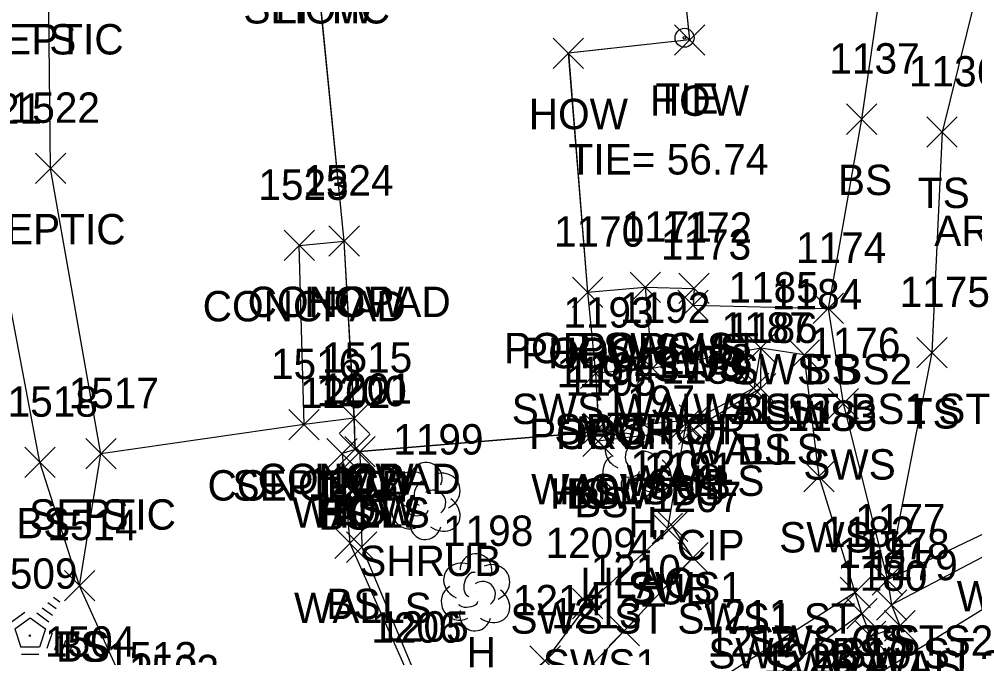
# Model space of a CAD drawing. Extents: x 1512665 to 1513714, y 110636 to 112816.
# Drawn here: x 1513101.2 to 1513164.2, y 110977 to 111019.1 of the extents above; entities that cross this region are included whole.
import ezdxf

# ---------------------------------------------------------------- set-up
doc = ezdxf.new("R2010")
doc.units = 0
for name, color, linetype in [('C_A', 7, 'Continuous'), ('C_C', 7, 'Continuous'), ('CBP', 7, 'Continuous'), ('L_A', 7, 'Continuous'), ('L_C', 7, 'Continuous'), ('L_I', 7, 'Continuous'), ('L_TIC', 7, 'Continuous'), ('LBC', 7, 'Continuous'), ('LBF', 7, 'Continuous'), ('LELB', 7, 'Continuous'), ('Level 13', 7, 'Continuous'), ('LS', 7, 'Continuous'), ('LSH', 7, 'Continuous'), ('LTC', 7, 'Continuous'), ('LTD', 7, 'Continuous'), ('LWS', 7, 'Continuous'), ('P_I', 7, 'Continuous'), ('PEU', 7, 'Continuous'), ('R_A', 7, 'Continuous'), ('R_I', 7, 'Continuous'), ('R_TIC', 7, 'Continuous'), ('RSW', 7, 'Continuous'), ('U_A', 7, 'Continuous'), ('U_C', 7, 'Continuous'), ('U_I', 7, 'Continuous'), ('U_TIC', 7, 'Continuous'), ('USA', 7, 'Continuous'), ('UUU', 7, 'Continuous')]:
    doc.layers.add(name, color=color, linetype=linetype)

msp = doc.modelspace()

# ---------------------------------------------------------------- linework, layer by layer
at = {"layer": 'CBP'}
for radius in [0.625, 0.0833]:
    msp.add_circle((1513145.031, 111017.845), radius, dxfattribs=at)
at = {"layer": 'L_TIC'}
for points in [[(1513144.361, 111016.708), (1513146.361, 111018.708)], [(1513146.361, 111016.708), (1513144.361, 111018.708)], [(1513136.385, 111015.829), (1513138.385, 111017.829)], [(1513138.385, 111015.829), (1513136.385, 111017.829)], [(1513155.691, 111011.489), (1513157.691, 111013.489)], [(1513157.691, 111011.489), (1513155.691, 111013.489)], [(1513160.988, 111010.639), (1513162.988, 111012.639)], [(1513162.988, 111010.639), (1513160.988, 111012.639)], [(1513118.654, 111003.177), (1513120.654, 111005.177)], [(1513120.654, 111003.177), (1513118.654, 111005.177)], [(1513121.614, 111003.463), (1513123.614, 111005.463)], [(1513123.614, 111003.463), (1513121.614, 111005.463)], [(1513121.614, 111003.463), (1513123.614, 111005.463)], [(1513123.614, 111003.463), (1513121.614, 111005.463)], [(1513137.645, 111000.096), (1513139.645, 111002.096)], [(1513139.645, 111000.096), (1513137.645, 111002.096)], [(1513137.645, 111000.096), (1513139.645, 111002.096)], [(1513139.645, 111000.096), (1513137.645, 111002.096)], [(1513141.447, 111000.421), (1513143.447, 111002.421)], [(1513143.447, 111000.421), (1513141.447, 111002.421)], [(1513153.494, 110999.03), (1513155.494, 111001.03)], [(1513155.494, 110999.03), (1513153.494, 111001.03)], [(1513149.05, 110996.419), (1513151.05, 110998.419)], [(1513151.05, 110996.419), (1513149.05, 110998.419)], [(1513149.05, 110996.419), (1513151.05, 110998.419)], [(1513151.05, 110996.419), (1513149.05, 110998.419)], [(1513160.319, 110996.122), (1513162.319, 110998.122)], [(1513162.319, 110996.122), (1513160.319, 110998.122)], [(1513141.906, 110995.079), (1513143.906, 110997.079)], [(1513143.906, 110995.079), (1513141.906, 110997.079)], [(1513138.172, 110994.766), (1513140.172, 110996.766)], [(1513140.172, 110994.766), (1513138.172, 110996.766)], [(1513138.172, 110994.766), (1513140.172, 110996.766)], [(1513140.172, 110994.766), (1513138.172, 110996.766)], [(1513148.586, 110993.774), (1513150.586, 110995.774)], [(1513150.586, 110993.774), (1513148.586, 110995.774)], [(1513149.035, 110993.75), (1513151.035, 110995.75)], [(1513151.035, 110993.75), (1513149.035, 110995.75)], [(1513122.275, 110991.806), (1513124.275, 110993.806)], [(1513124.275, 110991.806), (1513122.275, 110993.806)], [(1513122.275, 110991.806), (1513124.275, 110993.806)], [(1513124.275, 110991.806), (1513122.275, 110993.806)], [(1513118.973, 110991.381), (1513120.973, 110993.381)], [(1513120.973, 110991.381), (1513118.973, 110993.381)], [(1513138.383, 110991.132), (1513140.383, 110993.132)], [(1513140.383, 110991.132), (1513138.383, 110993.132)], [(1513138.383, 110991.132), (1513140.383, 110993.132)], [(1513140.383, 110991.132), (1513138.383, 110993.132)], [(1513144.678, 110991.69), (1513146.678, 110993.69)], [(1513146.678, 110991.69), (1513144.678, 110993.69)], [(1513137.775, 110990.845), (1513139.775, 110992.845)], [(1513139.775, 110990.845), (1513137.775, 110992.845)], [(1513137.775, 110990.845), (1513139.775, 110992.845)], [(1513139.775, 110990.845), (1513137.775, 110992.845)], [(1513144.641, 110991.07), (1513146.641, 110993.07)], [(1513146.641, 110991.07), (1513144.641, 110993.07)], [(1513138.327, 110990.282), (1513140.327, 110992.282)], [(1513140.327, 110990.282), (1513138.327, 110992.282)], [(1513105.594, 110989.463), (1513107.594, 110991.463)], [(1513107.594, 110989.463), (1513105.594, 110991.463)], [(1513121.48, 110989.47), (1513123.48, 110991.47)], [(1513123.48, 110989.47), (1513121.48, 110991.47)], [(1513122.337, 110989.753), (1513124.337, 110991.753)], [(1513124.337, 110989.753), (1513122.337, 110991.753)], [(1513122.337, 110989.753), (1513124.337, 110991.753)], [(1513124.337, 110989.753), (1513122.337, 110991.753)], [(1513122.648, 110989.593), (1513124.648, 110991.593)], [(1513124.648, 110989.593), (1513122.648, 110991.593)], [(1513122.648, 110989.593), (1513124.648, 110991.593)], [(1513124.648, 110989.593), (1513122.648, 110991.593)], [(1513101.575, 110988.899), (1513103.575, 110990.899)], [(1513103.575, 110988.899), (1513101.575, 110990.899)], [(1513121.993, 110983.577), (1513123.993, 110985.577)], [(1513123.993, 110983.577), (1513121.993, 110985.577)], [(1513122.771, 110983.314), (1513124.771, 110985.314)], [(1513124.771, 110983.314), (1513122.771, 110985.314)], [(1513157.395, 110981.164), (1513159.395, 110983.164)], [(1513159.395, 110981.164), (1513157.395, 110983.164)], [(1513157.395, 110981.164), (1513159.395, 110983.164)], [(1513159.395, 110981.164), (1513157.395, 110983.164)], [(1513104.188, 110980.774), (1513106.188, 110982.774)], [(1513106.188, 110980.774), (1513104.188, 110982.774)], [(1513104.188, 110980.774), (1513106.188, 110982.774)], [(1513106.188, 110980.774), (1513104.188, 110982.774)], [(1513155.276, 110980.329), (1513157.276, 110982.329)], [(1513157.276, 110980.329), (1513155.276, 110982.329)], [(1513157.665, 110979.511), (1513159.665, 110981.511)], [(1513159.665, 110979.511), (1513157.665, 110981.511)], [(1513155.717, 110978.943), (1513157.717, 110980.943)], [(1513157.717, 110978.943), (1513155.717, 110980.943)]]:
    msp.add_lwpolyline(points, dxfattribs=at)
at = {"layer": 'LBC'}
msp.add_lwpolyline([(1513118.388, 111046.131), (1513128.974, 111047.21), (1513141.844, 111048.525), (1513143.285, 111036.994), (1513150.612, 111037.656), (1513151.294, 111036.531), (1513151.864, 111031.982), (1513152.237, 111029.894), (1513144.204, 111028.943), (1513145.361, 111017.708), (1513137.385, 111016.829), (1513138.645, 111001.096), (1513139.172, 110995.766), (1513139.383, 110992.132), (1513138.775, 110991.845), (1513123.648, 110990.593), (1513123.337, 110990.753), (1513123.275, 110992.806), (1513122.614, 111004.463), (1513120.694, 111023.787), (1513118.555, 111043.769)], dxfattribs=at)
at = {"layer": 'LBF'}
msp.add_lwpolyline([(1513138.645, 111001.096), (1513142.447, 111001.421), (1513142.906, 110996.079), (1513139.172, 110995.766)], dxfattribs=at)
at = {"layer": 'LELB'}
for points in [[(1513170.214, 111130.816), (1513170.8, 111112.207), (1513173.531, 111089.539), (1513174.355, 111074.616), (1513179.798, 111058.724), (1513184.877, 111038.844), (1513186.524, 111012.71), (1513182.7, 110990.922), (1513167.492, 110986.513), (1513158.395, 110982.164)], [(1513152.471, 111070.911), (1513151.073, 111055.043), (1513161.472, 111056.619), (1513164.142, 111042.453), (1513166.779, 111030.992), (1513161.988, 111011.639), (1513161.319, 110997.122), (1513158.395, 110982.164)], [(1513105.188, 110981.774), (1513102.575, 110989.899), (1513098.9, 111009.187), (1513096.17, 111015.48), (1513093.494, 111029.55), (1513095.063, 111040.188), (1513092.913, 111045.41), (1513085.194, 111066.711)], [(1513153.398, 111047.966), (1513157.531, 111038.71), (1513159.125, 111029.326), (1513156.691, 111012.489), (1513154.494, 111000.03)], [(1513150.05, 110997.419), (1513150.035, 110994.75), (1513145.641, 110992.07), (1513139.327, 110991.282), (1513138.775, 110991.845)], [(1513123.337, 110990.753), (1513122.48, 110990.47), (1513122.993, 110984.577), (1513127.225, 110975.026), (1513127.998, 110970.168), (1513130.147, 110967.663)], [(1513116.012, 110958.893), (1513109.111, 110973.071), (1513105.188, 110981.774), (1513106.594, 110990.463)], [(1513156.276, 110981.329), (1513147.675, 110975.841), (1513130.86, 110966.117), (1513127.367, 110963.559), (1513113.24, 110946.252), (1513110.297, 110944.595), (1513100.487, 110942.417), (1513099.399, 110932.182), (1513097.199, 110922.304)]]:
    msp.add_lwpolyline(points, dxfattribs=at)
at = {"layer": 'Level 13'}
msp.add_lwpolyline([(1513123.644, 110990.606), (1513123.347, 110990.764), (1513123.285, 110992.81), (1513122.624, 111004.459), (1513120.705, 111023.788), (1513118.567, 111043.766), (1513118.402, 111046.123), (1513128.978, 111047.2), (1513141.835, 111048.514), (1513143.273, 111036.981), (1513150.611, 111037.648), (1513151.284, 111036.528), (1513151.853, 111031.979), (1513152.224, 111029.902), (1513144.191, 111028.956), (1513145.349, 111017.72), (1513137.373, 111016.842), (1513138.634, 111001.097), (1513139.163, 110995.765), (1513139.374, 110992.138), (1513138.775, 110991.854)], close=True, dxfattribs=at)
at = {"layer": 'LS'}
msp.add_lwpolyline([(1513123.275, 110992.806), (1513119.973, 110992.381), (1513119.654, 111004.177), (1513122.614, 111004.463)], dxfattribs=at)
at = {"layer": 'LSH'}
msp.add_line((1513127.977, 110987.411), (1513127.977, 110987.411), dxfattribs=at)
msp.add_line((1513127.977, 110987.411), (1513127.977, 110987.411), dxfattribs=at)
msp.add_arc((1513128.023, 110988.845), 1.047, 335.52715, 180.95627, dxfattribs=at)
for centre, major_axis, ratio, start_param, end_param in [((1513127.185, 110988.078), (1.21, -0.512), 0.895232, 1.570796, 4.712389), ((1513129.018, 110987.995), (-1.141, -0.483), 0.949671, 1.570796, 4.712389), ((1513127.768, 110987.87), (-0.208, -0.792), 0.645439, 3.141593, 6.283185), ((1513128.477, 110987.245), (-0.5, 0.667), 0.989748, 3.141593, 6.283185), ((1513126.893, 110986.703), (0.584, -1.042), 0.959034, 3.141593, 6.283185), ((1513128.977, 110986.578), (-1.09, 0.792), 0.841452, 1.570796, 4.712389), ((1513127.518, 110986.661), (-0.625, -0.083), 0.423636, 0, 3.141593), ((1513127.977, 110985.911), (0.265, 1.061), 0.942809, 1.570796, 4.712389)]:
    msp.add_ellipse(centre, major_axis=major_axis, ratio=ratio, start_param=start_param, end_param=end_param, dxfattribs=at)
at = {"layer": 'LTC'}
for p, q in [((1513103.107, 110980.678), (1513103.657, 110980.279)), ((1513103.479, 110981.027), (1513103.898, 110980.722)), ((1513100.709, 110979.389), (1513101.587, 110980.027)), ((1513102.365, 110979.982), (1513103.175, 110979.393)), ((1513102.737, 110980.33), (1513103.416, 110979.836)), ((1513100.934, 110978.934), (1513101.945, 110979.669)), ((1513101.945, 110979.669), (1513102.942, 110978.944)), ((1513100.934, 110978.934), (1513101.321, 110977.741)), ((1513102.942, 110978.944), (1513102.551, 110977.741)), ((1513103.38, 110978.673), (1513103.042, 110977.633)), ((1513103.824, 110978.422), (1513103.537, 110977.538)), ((1513104.269, 110978.172), (1513104.032, 110977.443)), ((1513102.551, 110977.741), (1513101.321, 110977.741)), ((1513104.713, 110977.922), (1513104.527, 110977.348)), ((1513102.513, 110977.241), (1513101.368, 110977.241))]:
    msp.add_line(p, q, dxfattribs=at)
at = {"layer": 'LTD'}
for p, q in [((1513141.89, 110989.956), (1513141.89, 110989.956)), ((1513141.89, 110989.956), (1513141.89, 110989.956)), ((1513131.249, 110981.395), (1513131.249, 110981.395)), ((1513131.249, 110981.395), (1513131.249, 110981.395))]:
    msp.add_line(p, q, dxfattribs=at)
for centre in [(1513141.937, 110991.39), (1513131.295, 110982.829)]:
    msp.add_arc(centre, 1.047, 335.52715, 180.95627, dxfattribs=at)
for centre, major_axis, ratio, start_param, end_param in [((1513141.098, 110990.622), (1.21, -0.512), 0.895232, 1.570796, 4.712389), ((1513142.932, 110990.539), (-1.141, -0.483), 0.949671, 1.570796, 4.712389), ((1513141.682, 110990.414), (-0.208, -0.792), 0.645439, 3.141593, 6.283185), ((1513142.39, 110989.789), (-0.5, 0.667), 0.989748, 3.141593, 6.283185), ((1513140.807, 110989.247), (0.584, -1.042), 0.959034, 3.141593, 6.283185), ((1513142.89, 110989.123), (-1.09, 0.792), 0.841452, 1.570796, 4.712389), ((1513141.89, 110988.456), (0.265, 1.061), 0.942809, 1.570796, 4.712389), ((1513141.432, 110989.206), (-0.625, -0.083), 0.423636, 0, 3.141593), ((1513130.457, 110982.062), (1.21, -0.512), 0.895232, 1.570796, 4.712389), ((1513132.29, 110981.979), (-1.141, -0.483), 0.949671, 1.570796, 4.712389), ((1513131.04, 110981.853), (-0.208, -0.792), 0.645439, 3.141593, 6.283185), ((1513131.749, 110981.229), (-0.5, 0.667), 0.989748, 3.141593, 6.283185), ((1513130.165, 110980.687), (0.584, -1.042), 0.959034, 3.141593, 6.283185), ((1513132.249, 110980.562), (-1.09, 0.792), 0.841452, 1.570796, 4.712389), ((1513130.79, 110980.645), (-0.625, -0.083), 0.423636, 0, 3.141593), ((1513131.249, 110979.895), (0.265, 1.061), 0.942809, 1.570796, 4.712389)]:
    msp.add_ellipse(centre, major_axis=major_axis, ratio=ratio, start_param=start_param, end_param=end_param, dxfattribs=at)
at = {"layer": 'LWS'}
for points in [[(1513150.05, 110997.419), (1513149.586, 110994.774), (1513145.678, 110992.69), (1513139.383, 110992.132)], [(1513190.646, 110994.729), (1513182.7, 110990.922), (1513167.412, 110985.094), (1513158.665, 110980.511)], [(1513123.648, 110990.593), (1513123.771, 110984.314), (1513127.636, 110975.095), (1513128.797, 110970.683)], [(1513156.717, 110979.943), (1513148.678, 110974.104), (1513134.451, 110961.665)]]:
    msp.add_lwpolyline(points, dxfattribs=at)
at = {"layer": 'PEU'}
msp.add_lwpolyline([(1513166.519, 110981.347), (1513152.909, 110972.975), (1513141.651, 110962.521), (1513132.856, 110956.743), (1513121.044, 110940.287), (1513117.581, 110922.155), (1513113.236, 110898.634), (1513114.597, 110873.193), (1513114.571, 110845.124), (1513110.002, 110827.884), (1513105.721, 110820.37), (1513100.887, 110809.465), (1513086.517, 110797.2)], dxfattribs=at)
at = {"layer": 'R_TIC'}
for points in [[(1513141.447, 111000.421), (1513143.447, 111002.421)], [(1513143.447, 111000.421), (1513141.447, 111002.421)], [(1513144.658, 111000.352), (1513146.658, 111002.352)], [(1513146.658, 111000.352), (1513144.658, 111002.352)], [(1513144.592, 110999.235), (1513146.592, 111001.235)], [(1513146.592, 110999.235), (1513144.592, 111001.235)], [(1513153.494, 110999.03), (1513155.494, 111001.03)], [(1513155.494, 110999.03), (1513153.494, 111001.03)], [(1513149.05, 110996.419), (1513151.05, 110998.419)], [(1513151.05, 110996.419), (1513149.05, 110998.419)], [(1513151.91, 110995.965), (1513153.91, 110997.965)], [(1513153.91, 110995.965), (1513151.91, 110997.965)], [(1513141.906, 110995.079), (1513143.906, 110997.079)], [(1513143.906, 110995.079), (1513141.906, 110997.079)], [(1513154.48, 110992.762), (1513156.48, 110994.762)], [(1513156.48, 110992.762), (1513154.48, 110994.762)], [(1513152.895, 110987.964), (1513154.895, 110989.964)], [(1513154.895, 110987.964), (1513152.895, 110989.964)], [(1513143.246, 110984.679), (1513145.246, 110986.679)], [(1513145.246, 110984.679), (1513143.246, 110986.679)], [(1513144.586, 110982.62), (1513146.586, 110984.62)], [(1513146.586, 110982.62), (1513144.586, 110984.62)], [(1513144.586, 110982.62), (1513146.586, 110984.62)], [(1513146.586, 110982.62), (1513144.586, 110984.62)], [(1513157.395, 110981.164), (1513159.395, 110983.164)], [(1513159.395, 110981.164), (1513157.395, 110983.164)], [(1513155.276, 110980.329), (1513157.276, 110982.329)], [(1513157.276, 110980.329), (1513155.276, 110982.329)], [(1513137.656, 110979.592), (1513139.656, 110981.592)], [(1513139.656, 110979.592), (1513137.656, 110981.592)], [(1513157.665, 110979.511), (1513159.665, 110981.511)], [(1513159.665, 110979.511), (1513157.665, 110981.511)], [(1513155.717, 110978.943), (1513157.717, 110980.943)], [(1513157.717, 110978.943), (1513155.717, 110980.943)], [(1513158.208, 110978.135), (1513160.208, 110980.135)], [(1513160.208, 110978.135), (1513158.208, 110980.135)], [(1513140.062, 110977.811), (1513142.062, 110979.811)], [(1513142.062, 110977.811), (1513140.062, 110979.811)], [(1513156.29, 110977.44), (1513158.29, 110979.44)], [(1513158.29, 110977.44), (1513156.29, 110979.44)], [(1513134.851, 110975.828), (1513136.851, 110977.828)], [(1513136.851, 110975.828), (1513134.851, 110977.828)]]:
    msp.add_lwpolyline(points, dxfattribs=at)
at = {"layer": 'RSW'}
for points in [[(1513142.447, 111001.421), (1513145.658, 111001.352), (1513145.592, 111000.235), (1513154.494, 111000.03), (1513155.48, 110993.762), (1513158.395, 110982.164), (1513158.665, 110980.511), (1513159.208, 110979.135), (1513157.29, 110978.44), (1513156.717, 110979.943), (1513156.276, 110981.329), (1513153.895, 110988.964), (1513152.91, 110996.965), (1513150.05, 110997.419), (1513142.906, 110996.079)], [(1513145.586, 110983.62), (1513144.246, 110985.679), (1513138.656, 110980.592), (1513135.851, 110976.828), (1513128.797, 110970.683), (1513130.147, 110967.663), (1513125.525, 110964.88), (1513127.367, 110963.559), (1513131.471, 110958.727)], [(1513145.586, 110983.62), (1513141.062, 110978.811), (1513138.384, 110975.976), (1513130.147, 110967.663), (1513130.86, 110966.117), (1513134.451, 110961.665), (1513131.471, 110958.727)]]:
    msp.add_lwpolyline(points, dxfattribs=at)
at = {"layer": 'U_TIC'}
for points in [[(1513102.277, 111008.248), (1513104.277, 111010.248)], [(1513104.277, 111008.248), (1513102.277, 111010.248)], [(1513118.973, 110991.381), (1513120.973, 110993.381)], [(1513120.973, 110991.381), (1513118.973, 110993.381)], [(1513144.114, 110991.452), (1513146.114, 110993.452)], [(1513146.114, 110991.452), (1513144.114, 110993.452)], [(1513105.594, 110989.463), (1513107.594, 110991.463)], [(1513107.594, 110989.463), (1513105.594, 110991.463)], [(1513142.906, 110984.543), (1513144.906, 110986.543)], [(1513144.906, 110984.543), (1513142.906, 110986.543)]]:
    msp.add_lwpolyline(points, dxfattribs=at)
at = {"layer": 'USA'}
msp.add_lwpolyline([(1513119.973, 110992.381), (1513106.594, 110990.463), (1513103.277, 111009.248), (1513103.152, 111021.748), (1513120.694, 111023.787)], dxfattribs=at)
at = {"layer": 'UUU'}
msp.add_lwpolyline([(1513145.114, 110992.452), (1513143.906, 110985.543)], dxfattribs=at)

# ---------------------------------------------------------------- texts
at = {"layer": 'C_A'}
msp.add_text('TIE', height=2, dxfattribs=at).set_placement((1513143.11, 111012.845))
at = {"layer": 'C_C'}
msp.add_text('TIE= 56.74', height=2, dxfattribs=at).set_placement((1513137.393, 111008.845))
at = {"layer": 'L_A'}
for s, p in [('HOW', (1513118.08, 111018.787)), ('TS', (1513101.561, 111016.748)), ('HOW', (1513142.747, 111012.708)), ('HOW', (1513134.771, 111011.829)), ('BS', (1513155.132, 111007.489)), ('TS', (1513160.397, 111006.639)), ('CONCPAD', (1513116.26, 110999.463)), ('HOW', (1513120, 110999.463)), ('CONCPAD', (1513113.299, 110999.177)), ('PORCH', (1513138.069, 110996.421)), ('PORCH', (1513134.267, 110996.096)), ('HOW', (1513136.031, 110996.096)), ('BS', (1513152.935, 110995.03)), ('WALLS', (1513145.593, 110992.419)), ('BS', (1513148.491, 110992.419)), ('TS', (1513159.729, 110992.122)), ('PORCH', (1513138.528, 110991.079)), ('PORCH', (1513134.794, 110990.766)), ('HOW', (1513136.558, 110990.766)), ('WALLS', (1513145.13, 110989.774)), ('BS', (1513148.476, 110989.75)), ('CONCPAD', (1513113.619, 110987.381)), ('CONCPAD', (1513116.921, 110987.806)), ('HOW', (1513120.661, 110987.806)), ('WALLS', (1513141.222, 110987.69)), ('WALLS', (1513134.926, 110987.132)), ('HOW', (1513136.16, 110986.845)), ('HOW', (1513136.769, 110987.132)), ('BS', (1513137.216, 110986.845)), ('BS', (1513144.082, 110987.07)), ('BS', (1513137.768, 110986.282)), ('TS', (1513105.003, 110985.463)), ('WALLS', (1513119.192, 110985.593)), ('HOW', (1513120.723, 110985.753)), ('BS', (1513120.921, 110985.47)), ('HOW', (1513121.034, 110985.593)), ('BS', (1513121.778, 110985.753)), ('BS', (1513101.016, 110984.899)), ('H', (1513141.323, 110984.956)), ('SHRUB', (1513123.606, 110982.411)), ('WALLS', (1513162.955, 110980.094)), ('WALLS', (1513119.314, 110979.314)), ('BS', (1513121.434, 110979.577)), ('TS', (1513103.598, 110976.774)), ('BS', (1513103.629, 110976.774)), ('TS', (1513156.804, 110977.164)), ('CS', (1513156.836, 110977.164)), ('H', (1513130.682, 110976.395)), ('BS', (1513154.717, 110976.329)), ('WALLS', (1513154.208, 110975.511))]:
    msp.add_text(s, height=2, dxfattribs=at).set_placement(p)
at = {"layer": 'L_C'}
msp.add_text('LILAC', height=2, dxfattribs=at).set_placement((1513138.166, 110980.956))
at = {"layer": 'L_I'}
for s, p in [('1137', (1513154.565, 111015.489)), ('1136', (1513159.807, 111014.639)), ('1521', (1513096.774, 111012.187)), ('1524', (1513119.921, 111007.463)), ('1524', (1513119.921, 111007.463)), ('1523', (1513116.961, 111007.177)), ('1171', (1513140.887, 111004.421)), ('1170', (1513136.432, 111004.096)), ('1170', (1513136.432, 111004.096)), ('1174', (1513152.368, 111003.03)), ('1185', (1513147.924, 111000.419)), ('1185', (1513147.924, 111000.419)), ('1175', (1513159.193, 111000.122)), ('1193', (1513137.046, 110998.766)), ('1193', (1513137.046, 110998.766)), ('1192', (1513140.78, 110999.079)), ('1187', (1513147.46, 110997.774)), ('1186', (1513147.854, 110997.75)), ('1515', (1513121.149, 110995.806)), ('1515', (1513121.149, 110995.806)), ('1188', (1513143.552, 110995.69)), ('1516', (1513117.792, 110995.381)), ('1194', (1513137.257, 110995.132)), ('1194', (1513137.257, 110995.132)), ('1189', (1513143.507, 110995.07)), ('1196', (1513136.594, 110994.845)), ('1196', (1513136.594, 110994.845)), ('1195', (1513137.201, 110994.282)), ('1201', (1513121.132, 110993.753)), ('1201', (1513121.132, 110993.753)), ('1517', (1513104.468, 110993.463)), ('1202', (1513119.709, 110993.47)), ('1200', (1513120.79, 110993.593)), ('1200', (1513120.79, 110993.593)), ('1518', (1513100.449, 110992.899)), ('1197', (1513139.764, 110992.956)), ('1199', (1513125.843, 110990.411)), ('1203', (1513120.222, 110987.577)), ('1204', (1513120.999, 110987.314)), ('1177', (1513156.269, 110985.164)), ('1177', (1513156.269, 110985.164)), ('1514', (1513103.062, 110984.774)), ('1514', (1513103.062, 110984.774)), ('1198', (1513129.123, 110984.395)), ('1182', (1513154.15, 110984.329)), ('1181', (1513155.158, 110982.943)), ('1178', (1513156.539, 110983.511)), ('1509', (1513099.106, 110981.578)), ('1211', (1513146.116, 110978.841)), ('1206', (1513124.398, 110978.026)), ('1205', (1513124.864, 110978.095)), ('1504', (1513102.914, 110977.103)), ('1212', (1513146.552, 110977.104)), ('1212', (1513146.552, 110977.104)), ('1513', (1513106.985, 110976.071)), ('1503', (1513108.429, 110975.227))]:
    msp.add_text(s, height=2, dxfattribs=at).set_placement(p)
at = {"layer": 'LTC'}
msp.add_text('.', height=1.037, rotation=270, dxfattribs=at).set_placement((1513101.828, 110978.682))
at = {"layer": 'P_I'}
msp.add_text('1223', height=2, dxfattribs=at).set_placement((1513150.216, 110975.975))
at = {"layer": 'R_A'}
for s, p in [('POR SWS ST', (1513133.132, 110996.421)), ('SWS', (1513143.028, 110996.352)), ('SWS', (1513142.962, 110995.235)), ('SWS BS2', (1513148.131, 110995.03)), ('SWS WALLS1 ST BS1 ST', (1513133.648, 110992.419)), ('SWS', (1513150.28, 110991.965)), ('SWS POR', (1513136.457, 110991.079)), ('SWS', (1513152.85, 110988.762)), ('SWS', (1513151.266, 110983.964)), ('SWS1', (1513141.286, 110980.679)), ('SWS ST SWS1 ST', (1513133.562, 110978.62)), ('SWS ST SWS1 ST', (1513133.562, 110978.62)), ('SWS CS TS2', (1513149.166, 110977.164)), ('SWS BS10 ST', (1513146.599, 110976.329)), ('SWS1', (1513135.695, 110975.592)), ('SWS WALLS', (1513150.303, 110975.511))]:
    msp.add_text(s, height=2, dxfattribs=at).set_placement(p)
at = {"layer": 'R_I'}
for s, p in [('1171', (1513140.887, 111004.421)), ('1172', (1513143.532, 111004.352)), ('1173', (1513143.466, 111003.235)), ('1174', (1513152.368, 111003.03)), ('1185', (1513147.924, 111000.419)), ('1184', (1513150.784, 110999.965)), ('1192', (1513140.78, 110999.079)), ('1176', (1513153.298, 110996.762)), ('1183', (1513151.769, 110991.964)), ('1208', (1513141.475, 110988.679)), ('1207', (1513142.814, 110986.62)), ('1207', (1513142.814, 110986.62)), ('1177', (1513156.269, 110985.164)), ('1182', (1513154.15, 110984.329)), ('1209', (1513135.876, 110983.592)), ('1181', (1513155.158, 110982.943)), ('1178', (1513156.539, 110983.511)), ('1210', (1513138.849, 110981.811)), ('1179', (1513157.075, 110982.135)), ('1180', (1513155.078, 110981.44)), ('1214', (1513133.725, 110979.828)), ('1213', (1513136.258, 110978.976))]:
    msp.add_text(s, height=2, dxfattribs=at).set_placement(p)
at = {"layer": 'U_A'}
for s, p in [('SEPTIC', (1513115.978, 111018.787)), ('SEPTIC', (1513098.435, 111016.748)), ('SEPTIC', (1513098.56, 111004.248)), ('SEPTIC', (1513115.257, 110987.381)), ('SUB', (1513142.586, 110987.452)), ('SEPTIC', (1513101.877, 110985.463)), ('SUB', (1513141.378, 110980.543))]:
    msp.add_text(s, height=2, dxfattribs=at).set_placement(p)
at = {"layer": 'U_C'}
for s, p in [('ARTESIAN', (1513161.474, 111004.139)), ('4" CIP', (1513141.342, 110983.452))]:
    msp.add_text(s, height=2, dxfattribs=at).set_placement(p)
at = {"layer": 'U_I'}
for s, p in [('1522', (1513100.584, 111012.248)), ('1516', (1513117.792, 110995.381)), ('1190', (1513142.901, 110995.452)), ('1517', (1513104.468, 110993.463)), ('1191', (1513142.347, 110988.543))]:
    msp.add_text(s, height=2, dxfattribs=at).set_placement(p)

doc.saveas('drawing.dxf')
